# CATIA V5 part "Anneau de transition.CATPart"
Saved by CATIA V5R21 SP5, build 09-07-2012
Part number: Anneau de transition
Bounding box of the stored display mesh (mm): x -2371.34 to 2371.34, y -2368.892 to 2368.892, z -377.37 to 823
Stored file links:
  \\etu.ad.univ-lorraine.fr\bordron1\Documents\Parts EPR\Anneau de transition.CATPart
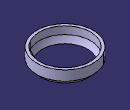
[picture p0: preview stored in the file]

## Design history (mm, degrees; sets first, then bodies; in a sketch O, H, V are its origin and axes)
AxisSystem1: origin (0, 0, 0), X (1, 0, 0), Y (0, 1, 0), Z (0, 0, 1)
Body1 (main body)
  Sketch1 on YZ plane of AxisSystem1, origin (0, 0, 0), H (0, 1, 0), V (0, 0, 1)
    line L1 (2140, 823) -> (2372, 823)
    line L2 (2372, 823) -> (2372, 0)
    line L3 (2140, 823) -> (2140, 196.7717)
    line L4 (2372, 0) -> (2222, 0)
    reference projected line E1 through (0, 0) direction (0, 1) from edge [ZX plane of AxisSystem1 | YZ plane of AxisSystem1]
    arc A1 centre (0, 935.7548) radius 2264 from (1898.7502, -297.308) to (2140, 196.7717) ccw
    point P6 (0, 935.7548)
    arc A2 centre (0, 935.7548) radius 2411 from (2022.0347, -377.3699) to (2222, 0) ccw
    line L5 (1898.7502, -297.308) -> (2022.0347, -377.3699)
    axis line L6 (1898.7502, -297.308) -> (-129.3596, 1019.7619)
    reference projected line E2 through (0, 0) direction (1, 0) from edge [YZ plane of AxisSystem1 | XY plane of AxisSystem1]
    reference intersected line E3 through (0, 0) direction (0, 1) from ZX plane of AxisSystem1
    length L2 = 823
    distance L3 E1 = 2140
    length L1 = 232
    radius A1 = 2264
    length L5 = 147
    length L4 = 150
    angle L6 E3 = 57
    horizontal: L1 H, L4 H
    vertical: L2 V, L3 V
    coincidence: P6 V, L6 P6, L4 E2
    parallelism: L6 L5
  Shaft1: profile Sketch1, axis edge [ZX plane of AxisSystem1 | YZ plane of AxisSystem1], angle 360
